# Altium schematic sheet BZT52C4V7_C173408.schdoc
size 127 x 101 mm
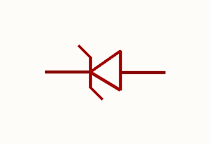
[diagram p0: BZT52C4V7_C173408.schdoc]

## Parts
D?  bzt52c4v7_c173408  [SOD-123_L2.8-W1.8-LS3.7-RD]  (value not drawn)

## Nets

Not connected (* = marked no-connect by the designer): D? 1 2

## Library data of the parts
D? = bzt52c4v7_c173408: 二极管配置:1个独立式;稳压值(标称值):4.7V;稳压值(范围):4.47V~4.94V;耗散功率(Pd):500mW;; Manufacturer: MDD(辰达半导体); AddInBom: yes; ModelId: 7884390a25fb4c08947731ebfba7e3f8; ModelTransform: 144.8816,62.992,0,0,0,0,0,0,0; Diode Configuration: 1个独立式; Zener Voltage(Nom): 4.7V; Reverse Leakage Current (Ir): 2uA@1V; Pd - Power Dissipation: 500mW; Impedance(Zzt): 130Ω; Tolerance: ±5%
